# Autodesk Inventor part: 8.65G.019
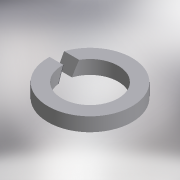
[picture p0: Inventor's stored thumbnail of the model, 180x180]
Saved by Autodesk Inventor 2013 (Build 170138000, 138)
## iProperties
Shininess: 25.0
Length Units: 11269
Angle Units: 11279
Time Units: 11290
Mass Units: 11283
Length Display Precision: 3
Angle Display Precision: 2
Created: 2001-04
Material: Steel, Mild
Description: Шайба 8.65Г.019 ГОСТ 6402-70
Document SubType Name: Modeling
Designer: tevgeniy
Density: 7.86 g/cm^3
Density: 0.0
Volumn: 0.0
Area: 0.0
PropertySet Name: Model Information
Control State: 0
Master: False
Checked Out: False
Last Check In Date: 2008-10-15
Checked Out Date: 2008-10-15
Author: tevgeniy
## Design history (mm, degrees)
node "ExtrusionBlind1" dims "d2" = 2, "d3" = 0
  sketch "Sketch1"
    geometry: C1 r 6.1 at (-266.435, -313.047)
    constraints: 1 centre point, 1 other
    dimensions: "d1" = 12.2 diameter of C1
node "Hole1" dims "d5" = 8.2, "d6" = 4, "d7" = 2, "d8" = 60 deg, "d9" = 8, "d10" = 118 deg
  sketch "Sketch2"
    geometry: C1 r 6.1 at (0, 0) reference
node "WorkAxis1"
workplane "Work Plane1"
workplane "Work Plane2"
node "WorkPlane1"
node "ExtrusionToFace1" dims "d18" = 0.13, "d19" = 0
  sketch "Sketch3"
    geometry: L1 (-17.369, -0.228)-(-17.369, -2); L2 (-15.369, 0.5)-(-17.369, -0.228); L3 (-15.369, -1.272)-(-15.369, 0.5); L4 (-17.369, -2)-(-15.369, -1.272); L5 (-7.684, 0)-(-25.053, 0); C1 r 6.1 at (-15.369, 0); C2 r 6.1 at (-17.369, 0)
    constraints: 10 end point, 2 centre point, 2 parallel, 1 vertical
    dimensions: "d13" = 0 horizontal distance of L2.start C1.centre; "d15" = 0 horizontal distance of L1.start C2.centre; "d17" = 160 deg angle of L4 L5
body "Solid1"
other parameters: "d0" = 12.2 (derived), "d4" = 0, "d11" = 0, "d12" = 0 (derived), "d14" = 0 (derived), "d16" = 160 deg (derived)
